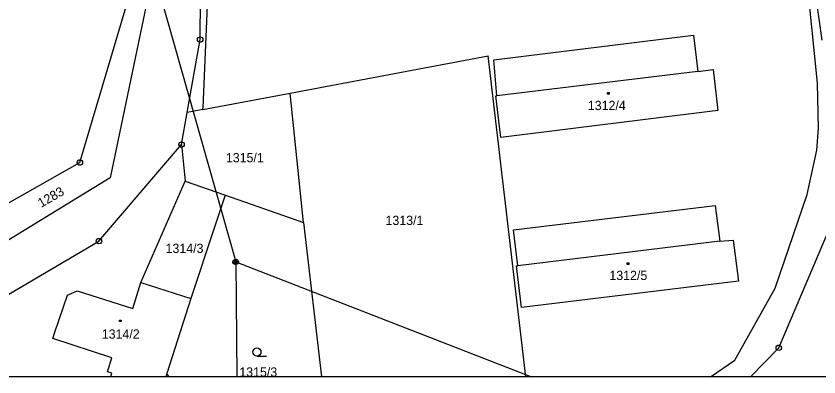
# Model space of a CAD drawing. Extents: x -468021 to -466942, y -1130484 to -1128584.
# Drawn here: x -467232 to -467084.7, y -1130484.4 to -1130418.2 of the extents above; entities that cross this region are included whole.
import ezdxf

# ---------------------------------------------------------------- set-up
doc = ezdxf.new("R2010")
doc.units = 0
doc.layers.add('Default', color=7, linetype='Continuous')
doc.layers.add('DKM', color=7, linetype='Continuous')

msp = doc.modelspace()

# ---------------------------------------------------------------- linework, layer by layer
at = {"layer": 'Default'}
msp.add_lwpolyline([(-468020.6, -1128583.91), (-466941.68, -1128583.91), (-466941.68, -1130484.41), (-468020.6, -1130484.41)], close=True, dxfattribs=at)
at = {"layer": 'DKM'}
for p, q in [((-467197.65, -1130434.98), (-467194.81, -1130368.83)), ((-467198.18, -1130422.55), (-467197.74, -1130370.4)), ((-467084.05, -1130422.63), (-467090.42, -1130378.87)), ((-467213.44, -1130386.52), (-467191.66, -1130463.32)), ((-467084.89, -1130430.56), (-467088.47, -1130395.87)), ((-467204.06, -1130396.89), (-467214.68, -1130447.92)), ((-467220.24, -1130445.09), (-467210.41, -1130411.87)), ((-467200.55, -1130435.91), (-467198.18, -1130422.55)), ((-467144.28, -1130426.25), (-467107.66, -1130421.73)), ((-467107.66, -1130421.73), (-467106.88, -1130428.39)), ((-467181.67, -1130432.37), (-467145.35, -1130425.56)), ((-467138.45, -1130484.41), (-467145.35, -1130425.56)), ((-467143.72, -1130432.87), (-467144.28, -1130426.25)), ((-467106.88, -1130428.39), (-467143.72, -1130432.87)), ((-467106.88, -1130428.39), (-467104.08, -1130428.05)), ((-467104.08, -1130428.05), (-467103.18, -1130435.54)), ((-467084.75, -1130438.82), (-467084.89, -1130430.56)), ((-467197.67, -1130435.37), (-467181.67, -1130432.37)), ((-467179.2, -1130456.09), (-467181.67, -1130432.37)), ((-467143.91, -1130432.89), (-467143.72, -1130432.87)), ((-467143.01, -1130440.48), (-467143.91, -1130432.89)), ((-467123.42, -1130432.24), (-467123.12, -1130432.24)), ((-467123.42, -1130432.54), (-467123.42, -1130432.24)), ((-467123.12, -1130432.54), (-467123.42, -1130432.54)), ((-467123.12, -1130432.24), (-467123.12, -1130432.54)), ((-467201.59, -1130441.8), (-467200.55, -1130435.91)), ((-467199.87, -1130435.78), (-467200.55, -1130435.91)), ((-467197.67, -1130435.37), (-467199.87, -1130435.78)), ((-467197.67, -1130435.37), (-467197.65, -1130434.98)), ((-467103.18, -1130435.54), (-467143.01, -1130440.48)), ((-467085.03, -1130442.8), (-467084.75, -1130438.82)), ((-467216.75, -1130459.5), (-467201.59, -1130441.8)), ((-467201.59, -1130441.8), (-467200.92, -1130448.5)), ((-467086.81, -1130450.94), (-467085.03, -1130442.8)), ((-467265.4, -1130470.62), (-467220.24, -1130445.09)), ((-467214.68, -1130447.92), (-467255.69, -1130472.89)), ((-467209.05, -1130467.07), (-467200.92, -1130448.5)), ((-467200.92, -1130448.5), (-467193.69, -1130451.03)), ((-467193.69, -1130451.03), (-467179.2, -1130456.09)), ((-467193.69, -1130451.03), (-467193.68, -1130451.24)), ((-467092.69, -1130468.16), (-467086.81, -1130450.94)), ((-467193.68, -1130451.24), (-467195.53, -1130456.97)), ((-467140.67, -1130457.45), (-467103.71, -1130452.97)), ((-467103.71, -1130452.97), (-467102.83, -1130459.51)), ((-467092.02, -1130479.06), (-467081.8, -1130455.03)), ((-467179.2, -1130456.09), (-467175.89, -1130484.41)), ((-467195.53, -1130456.97), (-467199.87, -1130470.04)), ((-467139.92, -1130464.03), (-467140.67, -1130457.45)), ((-467248.76, -1130478.29), (-467216.75, -1130459.5)), ((-467102.83, -1130459.51), (-467139.92, -1130464.03)), ((-467102.83, -1130459.51), (-467100.36, -1130459.33)), ((-467100.36, -1130459.33), (-467099.39, -1130466.87)), ((-467191.96, -1130462.92), (-467191.76, -1130462.82)), ((-467191.76, -1130462.82), (-467191.56, -1130462.82)), ((-467191.56, -1130462.82), (-467191.36, -1130462.92)), ((-467192.16, -1130463.22), (-467192.06, -1130463.02)), ((-467192.16, -1130463.42), (-467192.16, -1130463.22)), ((-467192.06, -1130463.62), (-467192.16, -1130463.42)), ((-467192.06, -1130463.02), (-467191.96, -1130462.92)), ((-467191.96, -1130463.72), (-467192.06, -1130463.62)), ((-467191.96, -1130463.12), (-467191.96, -1130463.52)), ((-467191.96, -1130463.52), (-467191.76, -1130463.62)), ((-467191.76, -1130463.82), (-467191.96, -1130463.72)), ((-467191.76, -1130463.62), (-467191.76, -1130463.02)), ((-467191.76, -1130463.02), (-467191.56, -1130463.02)), ((-467191.56, -1130463.82), (-467191.76, -1130463.82)), ((-467191.66, -1130463.32), (-467137.41, -1130484.41)), ((-467191.66, -1130463.32), (-467191.46, -1130484.41)), ((-467191.56, -1130463.02), (-467191.56, -1130463.62)), ((-467191.56, -1130463.62), (-467191.36, -1130463.52)), ((-467191.36, -1130463.72), (-467191.56, -1130463.82)), ((-467191.36, -1130462.92), (-467191.26, -1130463.02)), ((-467191.36, -1130463.52), (-467191.36, -1130463.12)), ((-467191.26, -1130463.62), (-467191.36, -1130463.72)), ((-467191.26, -1130463.02), (-467191.16, -1130463.22)), ((-467191.16, -1130463.42), (-467191.26, -1130463.62)), ((-467191.16, -1130463.22), (-467191.16, -1130463.42)), ((-467140.12, -1130464.06), (-467139.92, -1130464.03)), ((-467139.23, -1130471.67), (-467140.12, -1130464.06)), ((-467119.84, -1130463.47), (-467119.54, -1130463.47)), ((-467119.84, -1130463.77), (-467119.84, -1130463.47)), ((-467119.54, -1130463.77), (-467119.84, -1130463.77)), ((-467119.54, -1130463.47), (-467119.54, -1130463.77)), ((-467210.54, -1130471.89), (-467209.05, -1130467.07)), ((-467209.05, -1130467.07), (-467199.87, -1130470.04)), ((-467099.39, -1130466.87), (-467139.23, -1130471.67)), ((-467222.55, -1130469.41), (-467220.73, -1130468.61)), ((-467220.73, -1130468.61), (-467210.54, -1130471.89)), ((-467100.11, -1130481.34), (-467092.69, -1130468.16)), ((-467224.82, -1130476.22), (-467222.55, -1130469.41)), ((-467199.87, -1130470.04), (-467204.27, -1130483.79)), ((-467212.98, -1130473.97), (-467212.68, -1130473.97)), ((-467212.98, -1130474.27), (-467212.98, -1130473.97)), ((-467212.68, -1130474.27), (-467212.98, -1130474.27)), ((-467212.68, -1130473.97), (-467212.68, -1130474.27)), ((-467225.19, -1130477.33), (-467224.82, -1130476.22)), ((-467214.36, -1130480.9), (-467225.19, -1130477.33)), ((-467097.2, -1130484.41), (-467092.02, -1130479.06)), ((-467215.18, -1130483.48), (-467214.36, -1130480.9)), ((-467187.77, -1130480.59), (-467186.02, -1130480.59)), ((-467104.57, -1130484.41), (-467100.11, -1130481.34)), ((-467214.36, -1130483.74), (-467215.18, -1130483.48)), ((-467214.59, -1130484.41), (-467214.36, -1130483.74)), ((-467204.27, -1130483.79), (-467204.47, -1130484.41)), ((-467203.86, -1130484.41), (-467204.27, -1130483.79))]:
    msp.add_line(p, q, dxfattribs=at)
for centre, radius in [((-467198.18, -1130422.55), 0.5), ((-467198.18, -1130422.55), 0.01), ((-467201.59, -1130441.8), 0.5), ((-467201.59, -1130441.8), 0.01), ((-467220.24, -1130445.09), 0.5), ((-467220.24, -1130445.09), 0.01), ((-467216.75, -1130459.5), 0.5), ((-467216.75, -1130459.5), 0.01), ((-467092.02, -1130479.06), 0.5), ((-467187.77, -1130479.84), 0.75), ((-467092.02, -1130479.06), 0.01)]:
    msp.add_circle(centre, radius, dxfattribs=at)

# ---------------------------------------------------------------- texts
for s, p in [('1312/4', (-467127.05, -1130435.48)), ('1315/1', (-467193.46, -1130445.05)), ('1313/1', (-467164.17, -1130456.55)), ('1314/3', (-467204.53, -1130461.68)), ('1312/5', (-467123.1, -1130466.64)), ('1314/2', (-467216.23, -1130477.39)), ('1315/3', (-467191, -1130484.36))]:
    msp.add_text(s, height=1.7, dxfattribs=at).set_placement(p)
msp.add_text('1283', height=1.7, rotation=29.7148, dxfattribs=at).set_placement((-467227.36, -1130453.41))

doc.saveas('drawing.dxf')
